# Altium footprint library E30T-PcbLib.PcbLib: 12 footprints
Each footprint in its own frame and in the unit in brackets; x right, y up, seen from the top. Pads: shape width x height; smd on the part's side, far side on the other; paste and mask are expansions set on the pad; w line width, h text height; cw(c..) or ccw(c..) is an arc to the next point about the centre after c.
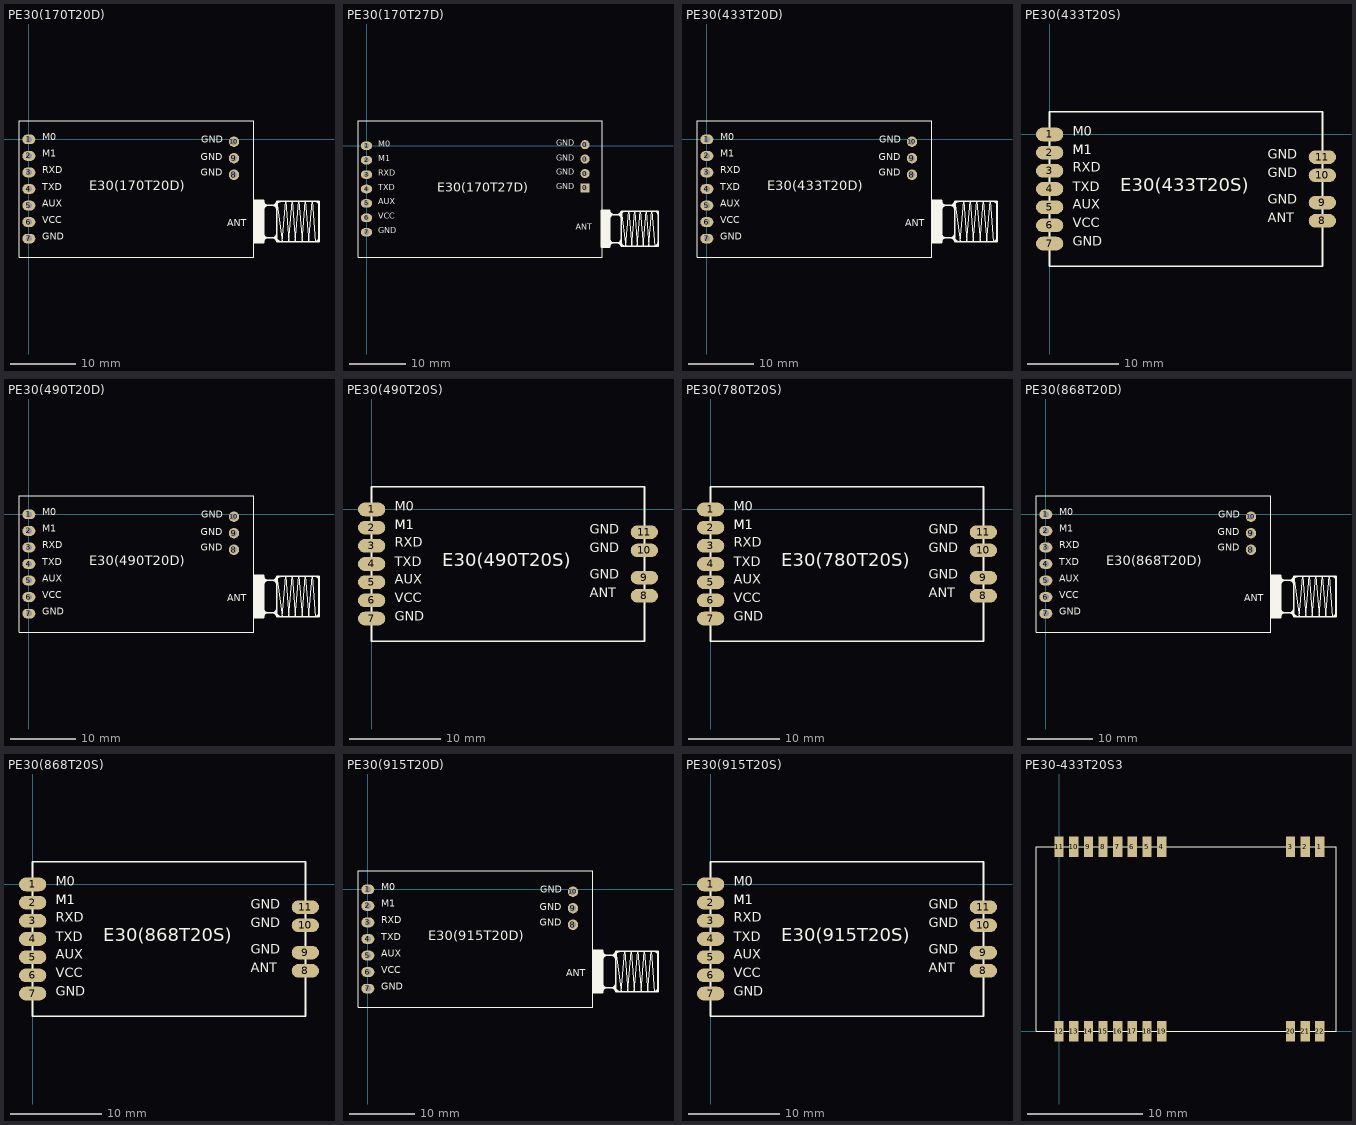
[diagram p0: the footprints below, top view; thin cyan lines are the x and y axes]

## PE30(170T20D) [mm] "36mm*21mm-D/SMA长度12.5mm"
pads (10):
  oval 2x1.5 hole 0.9: 1(0,0) 2(0,-2.54) 3(0,-5.08) 4(0,-7.62) 5(0,-10.16) 6(0,-12.7) 7(0,-15.24)
  round 1.6 hole 1: 8(31.49,-5.43) 9(31.49,-2.89) 10(31.49,-0.35)
Top Overlay:
  rectangle: 34.54,-15.865 36.04,-9.365
  rectangle: 34.54,-15.87 36.04,-9.37
  lines w0.1: 38.89,-15.72 38.04,-9.52 38.89,-15.72 ; 38.89,-15.72 39.41,-9.52 ; 38.89,-15.72 39.41,-9.52 ; 39.41,-9.52 39.92,-15.72 ; 39.41,-9.52 39.92,-15.72 ; 39.92,-15.72 40.43,-9.52 ; 39.92,-15.72 40.43,-9.52 ; 40.43,-9.52 40.91,-15.72 ; 40.43,-9.52 40.91,-15.72 ; 40.91,-15.72 41.43,-9.52 ; 40.91,-15.72 41.43,-9.52 ; 41.43,-9.52 41.94,-15.72 ; 41.43,-9.52 41.94,-15.72 ; 41.94,-15.72 42.43,-9.52 ; 41.94,-15.72 42.43,-9.52 ; 42.43,-9.52 42.95,-15.72 ; 42.43,-9.52 42.95,-15.72 ; 42.95,-15.72 43.47,-9.52 ; 42.95,-15.72 43.47,-9.52 ; 43.47,-9.52 43.98,-15.72 43.47,-9.52 ; -1.51,-18.12 -1.51,2.88 34.558,2.88 34.558,-18.12 -1.51,-18.12
  lines w0.254: 34.54,-15.87 34.54,-9.37 ; 34.54,-15.87 36.04,-15.87 ; 34.54,-15.87 34.54,-9.37 ; 34.54,-15.87 36.04,-15.87 ; 34.54,-9.37 36.04,-9.37 ; 34.54,-9.37 36.04,-9.37 ; 36.04,-15.87 36.04,-9.37 ; 36.04,-15.87 36.04,-9.37 ; 36.04,-14.47 ccw(c36.69,-14.47) 36.69,-15.12 ; 36.04,-14.47 ccw(c36.69,-14.47) 36.69,-15.12 ; 36.04,-14.47 36.04,-14.1 36.04,-14.47 ; 36.04,-10.82 cw(c36.74,-10.82) 36.74,-10.12 ; 36.04,-10.82 cw(c36.74,-10.82) 36.74,-10.12 ; 36.04,-10.82 36.04,-11.74 36.04,-10.82 ; 36.04,-9.49 ccw(c36.67,-9.49) 36.67,-10.12 ; 36.04,-9.49 ccw(c36.67,-9.49) 36.67,-10.12 ; 36.04,-9.49 36.04,-9.37 ; 36.04,-9.49 36.04,-9.37 ; 36.59,-15.12 ccw(c36.59,-15.67) 36.04,-15.67 cw(c36.59,-15.67) 36.59,-15.12 ; 36.59,-15.12 37.44,-15.12 ; 36.59,-15.12 37.44,-15.12 ; 36.67,-10.12 37.44,-10.12 ; 36.67,-10.12 37.44,-10.12 ; 36.69,-15.12 37.41,-15.12 ; 36.69,-15.12 37.41,-15.12 ; 36.74,-10.12 37.44,-10.12 ; 36.74,-10.12 37.44,-10.12 ; 37.41,-15.12 ccw(c37.41,-14.49) 38.04,-14.49 cw(c37.41,-14.49) 37.41,-15.12 ; 37.44,-15.12 cw(c37.44,-15.72) 38.04,-15.72 ; 37.44,-15.12 cw(c37.44,-15.72) 38.04,-15.72 ; 37.44,-10.12 ccw(c37.44,-9.52) 38.04,-9.52 ; 37.44,-10.12 cw(c37.44,-10.72) 38.04,-10.72 ccw(c37.44,-10.72) 37.44,-10.12 ; 37.44,-10.12 ccw(c37.44,-9.52) 38.04,-9.52 ; 38.04,-15.72 44.54,-15.72 ; 38.04,-15.72 38.04,-9.52 ; 38.04,-15.72 44.54,-15.72 ; 38.04,-15.72 38.04,-9.52 ; 38.04,-9.52 44.54,-9.52 ; 38.04,-9.52 44.54,-9.52 ; 38.72,-15.72 cw(c38.72,-15.04) 38.04,-15.04 ccw(c38.72,-15.04) 38.72,-15.72 ; 38.72,-15.72 38.87,-15.72 38.72,-15.72 ; 43.92,-15.72 ccw(c43.92,-15.1) 44.54,-15.1 cw(c43.92,-15.1) 43.92,-15.72 ; 43.92,-15.72 43.69,-15.72 43.92,-15.72 ; 44,-9.52 cw(c44,-10.06) 44.54,-10.06 ccw(c44,-10.06) 44,-9.52 ; 44,-9.52 43.6,-9.52 44,-9.52 ; 44.54,-15.72 44.54,-9.52 ; 44.54,-15.72 44.54,-9.52 ; 35.87,-15.12 38.04,-15.12 35.87,-15.12 ; 36.04,-10.12 38.04,-10.12 36.04,-10.12 ; 38.04,-10.13 cw(c38.65,-10.13) 38.65,-9.52 ccw(c38.65,-10.13) 38.04,-10.13
  text "E30(170T20D)" at 9.271,-8.382 h2.5
  text "GND" at 26.416,-5.969 h1.8
  text "GND" at 26.416,-3.556 h1.8
  text "GND" at 26.447,-0.921 h1.8
  text "ANT" at 30.48,-13.716 h1.8
  text "M0" at 2.063,-0.54 h1.8
  text "M1" at 2.063,-3.08 h1.8
  text "RXD" at 2.063,-5.62 h1.8
  text "TXD" at 2.063,-8.16 h1.8
  text "AUX" at 2.063,-10.7 h1.8
  text "VCC" at 2.063,-13.24 h1.8
  text "GND" at 2.063,-15.78 h1.8

## PE30(170T27D) [mm] "43MM*24mm-D//SMA长度12.5mm"
pads (11):
  rect 1.6x1.6 hole 0.9: 0(38.5,-7.43)
  round 1.6 hole 0.9: 0(38.5,-4.89) 0(38.5,-2.35) 0(38.5,0.19)
  oval 2x1.5 hole 0.9: 1(0,0) 2(0,-2.54) 3(0,-5.08) 4(0,-7.62) 5(0,-10.16) 6(0,-12.7) 7(0,-15.24)
Top Overlay:
  rectangle: 41.35,-17.87 42.85,-11.37
  rectangle: 41.35,-17.865 42.85,-11.365
  lines w0.1: 45.7,-17.72 46.22,-11.52 ; 45.7,-17.72 44.85,-11.52 45.7,-17.72 ; 45.7,-17.72 46.22,-11.52 ; 46.22,-11.52 46.73,-17.72 ; 46.22,-11.52 46.73,-17.72 ; 46.73,-17.72 47.24,-11.52 ; 46.73,-17.72 47.24,-11.52 ; 47.24,-11.52 47.72,-17.72 ; 47.24,-11.52 47.72,-17.72 ; 47.72,-17.72 48.24,-11.52 ; 47.72,-17.72 48.24,-11.52 ; 48.24,-11.52 48.75,-17.72 ; 48.24,-11.52 48.75,-17.72 ; 48.75,-17.72 49.24,-11.52 ; 48.75,-17.72 49.24,-11.52 ; 49.24,-11.52 49.76,-17.72 ; 49.24,-11.52 49.76,-17.72 ; 49.76,-17.72 50.28,-11.52 ; 49.76,-17.72 50.28,-11.52 ; 50.28,-11.52 50.79,-17.72 50.28,-11.52 ; -1.5,-19.62 41.5,-19.62 41.5,4.38 -1.5,4.38 -1.5,-19.62
  lines w0.254: 41.35,-17.87 42.85,-17.87 ; 41.35,-17.87 41.35,-11.37 ; 41.35,-17.87 42.85,-17.87 ; 41.35,-17.87 41.35,-11.37 ; 41.35,-11.37 42.85,-11.37 ; 41.35,-11.37 42.85,-11.37 ; 42.85,-17.87 42.85,-11.37 ; 42.85,-17.87 42.85,-11.37 ; 42.85,-16.47 ccw(c43.5,-16.47) 43.5,-17.12 ; 42.85,-16.47 ccw(c43.5,-16.47) 43.5,-17.12 ; 42.85,-16.47 42.85,-16.1 42.85,-16.47 ; 42.85,-12.82 cw(c43.55,-12.82) 43.55,-12.12 ; 42.85,-12.82 cw(c43.55,-12.82) 43.55,-12.12 ; 42.85,-12.82 42.85,-13.74 42.85,-12.82 ; 42.85,-11.49 ccw(c43.48,-11.49) 43.48,-12.12 ; 42.85,-11.49 ccw(c43.48,-11.49) 43.48,-12.12 ; 42.85,-11.49 42.85,-11.37 ; 42.85,-11.49 42.85,-11.37 ; 43.4,-17.12 ccw(c43.4,-17.67) 42.85,-17.67 cw(c43.4,-17.67) 43.4,-17.12 ; 43.4,-17.12 44.25,-17.12 ; 43.4,-17.12 44.25,-17.12 ; 43.48,-12.12 44.25,-12.12 ; 43.48,-12.12 44.25,-12.12 ; 43.5,-17.12 44.22,-17.12 ; 43.5,-17.12 44.22,-17.12 ; 43.55,-12.12 44.25,-12.12 ; 43.55,-12.12 44.25,-12.12 ; 44.22,-17.12 ccw(c44.22,-16.49) 44.85,-16.49 cw(c44.22,-16.49) 44.22,-17.12 ; 44.25,-17.12 cw(c44.25,-17.72) 44.85,-17.72 ; 44.25,-17.12 cw(c44.25,-17.72) 44.85,-17.72 ; 44.25,-12.12 cw(c44.25,-12.72) 44.85,-12.72 ccw(c44.25,-12.72) 44.25,-12.12 ; 44.25,-12.12 ccw(c44.25,-11.52) 44.85,-11.52 ; 44.25,-12.12 ccw(c44.25,-11.52) 44.85,-11.52 ; 44.85,-17.72 44.85,-11.52 ; 44.85,-17.72 51.35,-17.72 ; 44.85,-17.72 44.85,-11.52 ; 44.85,-17.72 51.35,-17.72 ; 44.85,-11.52 51.35,-11.52 ; 44.85,-11.52 51.35,-11.52 ; 45.53,-17.72 cw(c45.53,-17.04) 44.85,-17.04 ccw(c45.53,-17.04) 45.53,-17.72 ; 45.53,-17.72 45.68,-17.72 45.53,-17.72 ; 50.73,-17.72 ccw(c50.73,-17.1) 51.35,-17.1 cw(c50.73,-17.1) 50.73,-17.72 ; 50.73,-17.72 50.5,-17.72 50.73,-17.72 ; 50.81,-11.52 cw(c50.81,-12.06) 51.35,-12.06 ccw(c50.81,-12.06) 50.81,-11.52 ; 50.81,-11.52 50.41,-11.52 50.81,-11.52 ; 51.35,-17.72 51.35,-11.52 ; 51.35,-17.72 51.35,-11.52 ; 42.68,-17.12 44.85,-17.12 42.68,-17.12 ; 42.85,-12.12 44.85,-12.12 42.85,-12.12 ; 44.85,-12.13 cw(c45.46,-12.13) 45.46,-11.52 ccw(c45.46,-12.13) 44.85,-12.13
  text "E30(170T27D)" at 12.446,-8.763 h2.8
  text "ANT" at 36.83,-15.19 h1.8
  text "M0" at 2.063,-0.54 h1.8
  text "M1" at 2.063,-3.08 h1.8
  text "RXD" at 2.063,-5.62 h1.8
  text "TXD" at 2.063,-8.16 h1.8
  text "AUX" at 2.063,-10.7 h1.8
  text "VCC" at 2.063,-13.24 h1.8
  text "GND" at 2.063,-15.78 h1.8
  text "GND" at 33.426,-5.429 h1.8
  text "GND" at 33.426,-3.016 h1.8
  text "GND" at 33.457,-0.381 h1.8
  text "GND" at 33.457,-8.001 h1.8

## PE30(433T20D) [mm] "36mm*21mm-D//SMA长度12.5mm"
pads (10):
  oval 2x1.5 hole 0.9: 1(0,0) 2(0,-2.54) 3(0,-5.08) 4(0,-7.62) 5(0,-10.16) 6(0,-12.7) 7(0,-15.24)
  round 1.6 hole 1: 8(31.49,-5.43) 9(31.49,-2.89) 10(31.49,-0.35)
Top Overlay:
  rectangle: 34.54,-15.87 36.04,-9.37
  rectangle: 34.54,-15.865 36.04,-9.365
  lines w0.1: 38.89,-15.72 39.41,-9.52 ; 38.89,-15.72 38.04,-9.52 38.89,-15.72 ; 38.89,-15.72 39.41,-9.52 ; 39.41,-9.52 39.92,-15.72 ; 39.41,-9.52 39.92,-15.72 ; 39.92,-15.72 40.43,-9.52 ; 39.92,-15.72 40.43,-9.52 ; 40.43,-9.52 40.91,-15.72 ; 40.43,-9.52 40.91,-15.72 ; 40.91,-15.72 41.43,-9.52 ; 40.91,-15.72 41.43,-9.52 ; 41.43,-9.52 41.94,-15.72 ; 41.43,-9.52 41.94,-15.72 ; 41.94,-15.72 42.43,-9.52 ; 41.94,-15.72 42.43,-9.52 ; 42.43,-9.52 42.95,-15.72 ; 42.43,-9.52 42.95,-15.72 ; 42.95,-15.72 43.47,-9.52 ; 42.95,-15.72 43.47,-9.52 ; 43.47,-9.52 43.98,-15.72 43.47,-9.52 ; -1.51,-18.12 34.558,-18.12 34.558,2.88 -1.51,2.88 -1.51,-18.12
  lines w0.254: 34.54,-15.87 36.04,-15.87 ; 34.54,-15.87 34.54,-9.37 ; 34.54,-15.87 36.04,-15.87 ; 34.54,-15.87 34.54,-9.37 ; 34.54,-9.37 36.04,-9.37 ; 34.54,-9.37 36.04,-9.37 ; 36.04,-15.87 36.04,-9.37 ; 36.04,-15.87 36.04,-9.37 ; 36.04,-14.47 ccw(c36.69,-14.47) 36.69,-15.12 ; 36.04,-14.47 ccw(c36.69,-14.47) 36.69,-15.12 ; 36.04,-14.47 36.04,-14.1 36.04,-14.47 ; 36.04,-10.82 cw(c36.74,-10.82) 36.74,-10.12 ; 36.04,-10.82 cw(c36.74,-10.82) 36.74,-10.12 ; 36.04,-10.82 36.04,-11.74 36.04,-10.82 ; 36.04,-9.49 ccw(c36.67,-9.49) 36.67,-10.12 ; 36.04,-9.49 ccw(c36.67,-9.49) 36.67,-10.12 ; 36.04,-9.49 36.04,-9.37 ; 36.04,-9.49 36.04,-9.37 ; 36.59,-15.12 ccw(c36.59,-15.67) 36.04,-15.67 cw(c36.59,-15.67) 36.59,-15.12 ; 36.59,-15.12 37.44,-15.12 ; 36.59,-15.12 37.44,-15.12 ; 36.67,-10.12 37.44,-10.12 ; 36.67,-10.12 37.44,-10.12 ; 36.69,-15.12 37.41,-15.12 ; 36.69,-15.12 37.41,-15.12 ; 36.74,-10.12 37.44,-10.12 ; 36.74,-10.12 37.44,-10.12 ; 37.41,-15.12 ccw(c37.41,-14.49) 38.04,-14.49 cw(c37.41,-14.49) 37.41,-15.12 ; 37.44,-15.12 cw(c37.44,-15.72) 38.04,-15.72 ; 37.44,-15.12 cw(c37.44,-15.72) 38.04,-15.72 ; 37.44,-10.12 cw(c37.44,-10.72) 38.04,-10.72 ccw(c37.44,-10.72) 37.44,-10.12 ; 37.44,-10.12 ccw(c37.44,-9.52) 38.04,-9.52 ; 37.44,-10.12 ccw(c37.44,-9.52) 38.04,-9.52 ; 38.04,-15.72 38.04,-9.52 ; 38.04,-15.72 44.54,-15.72 ; 38.04,-15.72 38.04,-9.52 ; 38.04,-15.72 44.54,-15.72 ; 38.04,-9.52 44.54,-9.52 ; 38.04,-9.52 44.54,-9.52 ; 38.72,-15.72 cw(c38.72,-15.04) 38.04,-15.04 ccw(c38.72,-15.04) 38.72,-15.72 ; 38.72,-15.72 38.87,-15.72 38.72,-15.72 ; 43.92,-15.72 ccw(c43.92,-15.1) 44.54,-15.1 cw(c43.92,-15.1) 43.92,-15.72 ; 43.92,-15.72 43.69,-15.72 43.92,-15.72 ; 44,-9.52 cw(c44,-10.06) 44.54,-10.06 ccw(c44,-10.06) 44,-9.52 ; 44,-9.52 43.6,-9.52 44,-9.52 ; 44.54,-15.72 44.54,-9.52 ; 44.54,-15.72 44.54,-9.52 ; 35.87,-15.12 38.04,-15.12 35.87,-15.12 ; 36.04,-10.12 38.04,-10.12 36.04,-10.12 ; 38.04,-10.13 cw(c38.65,-10.13) 38.65,-9.52 ccw(c38.65,-10.13) 38.04,-10.13
  text "GND" at 2.063,-15.78 h1.8
  text "VCC" at 2.063,-13.24 h1.8
  text "AUX" at 2.063,-10.7 h1.8
  text "TXD" at 2.063,-8.16 h1.8
  text "RXD" at 2.063,-5.62 h1.8
  text "M1" at 2.063,-3.08 h1.8
  text "M0" at 2.063,-0.54 h1.8
  text "ANT" at 30.48,-13.716 h1.8
  text "GND" at 26.447,-0.921 h1.8
  text "GND" at 26.416,-3.556 h1.8
  text "GND" at 26.416,-5.969 h1.8
  text "E30(433T20D)" at 9.271,-8.382 h2.5

## PE30(433T20S) [mm] "30mm*17mm*3.5mm-S"
pads (11):
  oval 3x1.5 smd: 1(0,0) 2(0,-2) 3(0,-4) 4(0,-6) 5(0,-8) 6(0,-10) 7(0,-12) 8(30,-9.5) 9(30,-7.5) 10(30,-4.5) 11(30,-2.5)
Top Overlay:
  lines w0.2: 0,-14.5 0,2.5 30,2.5 30,-14.5 0,-14.5
  text "E30(433T20S)" at 7.761,-6.762 h2.5
  text "AUX" at 2.554,-8.54 h1.8
  text "M0" at 2.554,-0.539 h1.8
  text "M1" at 2.554,-2.571 h1.8
  text "M1" at 2.554,-2.571 h1.8
  text "RXD" at 2.554,-4.476 h1.8
  text "TXD" at 2.554,-6.635 h1.8
  text "VCC" at 2.554,-10.572 h1.8
  text "GND" at 2.554,-12.604 h1.8
  text "GND" at 24.017,-3.079 h1.8
  text "GND" at 24.017,-5.111 h1.8
  text "GND" at 24.017,-8.032 h1.8
  text "ANT" at 24.017,-10.064 h1.8

## PE30(490T20D) [mm] "36mm*21mm-D//SMA长度12.5mm"
pads (10):
  oval 2x1.5 hole 0.9: 1(0,0) 2(0,-2.54) 3(0,-5.08) 4(0,-7.62) 5(0,-10.16) 6(0,-12.7) 7(0,-15.24)
  round 1.6 hole 1: 8(31.49,-5.43) 9(31.49,-2.89) 10(31.49,-0.35)
Top Overlay:
  rectangle: 34.54,-15.865 36.04,-9.365
  rectangle: 34.54,-15.87 36.04,-9.37
  lines w0.1: 38.89,-15.72 38.04,-9.52 38.89,-15.72 ; 38.89,-15.72 39.41,-9.52 ; 38.89,-15.72 39.41,-9.52 ; 39.41,-9.52 39.92,-15.72 ; 39.41,-9.52 39.92,-15.72 ; 39.92,-15.72 40.43,-9.52 ; 39.92,-15.72 40.43,-9.52 ; 40.43,-9.52 40.91,-15.72 ; 40.43,-9.52 40.91,-15.72 ; 40.91,-15.72 41.43,-9.52 ; 40.91,-15.72 41.43,-9.52 ; 41.43,-9.52 41.94,-15.72 ; 41.43,-9.52 41.94,-15.72 ; 41.94,-15.72 42.43,-9.52 ; 41.94,-15.72 42.43,-9.52 ; 42.43,-9.52 42.95,-15.72 ; 42.43,-9.52 42.95,-15.72 ; 42.95,-15.72 43.47,-9.52 ; 42.95,-15.72 43.47,-9.52 ; 43.47,-9.52 43.98,-15.72 43.47,-9.52 ; -1.51,-18.12 -1.51,2.88 34.558,2.88 34.558,-18.12 -1.51,-18.12
  lines w0.254: 34.54,-15.87 34.54,-9.37 ; 34.54,-15.87 36.04,-15.87 ; 34.54,-15.87 34.54,-9.37 ; 34.54,-15.87 36.04,-15.87 ; 34.54,-9.37 36.04,-9.37 ; 34.54,-9.37 36.04,-9.37 ; 36.04,-15.87 36.04,-9.37 ; 36.04,-15.87 36.04,-9.37 ; 36.04,-14.47 ccw(c36.69,-14.47) 36.69,-15.12 ; 36.04,-14.47 ccw(c36.69,-14.47) 36.69,-15.12 ; 36.04,-14.47 36.04,-14.1 36.04,-14.47 ; 36.04,-10.82 cw(c36.74,-10.82) 36.74,-10.12 ; 36.04,-10.82 cw(c36.74,-10.82) 36.74,-10.12 ; 36.04,-10.82 36.04,-11.74 36.04,-10.82 ; 36.04,-9.49 ccw(c36.67,-9.49) 36.67,-10.12 ; 36.04,-9.49 ccw(c36.67,-9.49) 36.67,-10.12 ; 36.04,-9.49 36.04,-9.37 ; 36.04,-9.49 36.04,-9.37 ; 36.59,-15.12 ccw(c36.59,-15.67) 36.04,-15.67 cw(c36.59,-15.67) 36.59,-15.12 ; 36.59,-15.12 37.44,-15.12 ; 36.59,-15.12 37.44,-15.12 ; 36.67,-10.12 37.44,-10.12 ; 36.67,-10.12 37.44,-10.12 ; 36.69,-15.12 37.41,-15.12 ; 36.69,-15.12 37.41,-15.12 ; 36.74,-10.12 37.44,-10.12 ; 36.74,-10.12 37.44,-10.12 ; 37.41,-15.12 ccw(c37.41,-14.49) 38.04,-14.49 cw(c37.41,-14.49) 37.41,-15.12 ; 37.44,-15.12 cw(c37.44,-15.72) 38.04,-15.72 ; 37.44,-15.12 cw(c37.44,-15.72) 38.04,-15.72 ; 37.44,-10.12 ccw(c37.44,-9.52) 38.04,-9.52 ; 37.44,-10.12 cw(c37.44,-10.72) 38.04,-10.72 ccw(c37.44,-10.72) 37.44,-10.12 ; 37.44,-10.12 ccw(c37.44,-9.52) 38.04,-9.52 ; 38.04,-15.72 44.54,-15.72 ; 38.04,-15.72 38.04,-9.52 ; 38.04,-15.72 44.54,-15.72 ; 38.04,-15.72 38.04,-9.52 ; 38.04,-9.52 44.54,-9.52 ; 38.04,-9.52 44.54,-9.52 ; 38.72,-15.72 cw(c38.72,-15.04) 38.04,-15.04 ccw(c38.72,-15.04) 38.72,-15.72 ; 38.72,-15.72 38.87,-15.72 38.72,-15.72 ; 43.92,-15.72 ccw(c43.92,-15.1) 44.54,-15.1 cw(c43.92,-15.1) 43.92,-15.72 ; 43.92,-15.72 43.69,-15.72 43.92,-15.72 ; 44,-9.52 cw(c44,-10.06) 44.54,-10.06 ccw(c44,-10.06) 44,-9.52 ; 44,-9.52 43.6,-9.52 44,-9.52 ; 44.54,-15.72 44.54,-9.52 ; 44.54,-15.72 44.54,-9.52 ; 35.87,-15.12 38.04,-15.12 35.87,-15.12 ; 36.04,-10.12 38.04,-10.12 36.04,-10.12 ; 38.04,-10.13 cw(c38.65,-10.13) 38.65,-9.52 ccw(c38.65,-10.13) 38.04,-10.13
  text "E30(490T20D)" at 9.271,-8.382 h2.5
  text "GND" at 26.416,-5.969 h1.8
  text "GND" at 26.416,-3.556 h1.8
  text "GND" at 26.447,-0.921 h1.8
  text "ANT" at 30.48,-13.716 h1.8
  text "M0" at 2.063,-0.54 h1.8
  text "M1" at 2.063,-3.08 h1.8
  text "RXD" at 2.063,-5.62 h1.8
  text "TXD" at 2.063,-8.16 h1.8
  text "AUX" at 2.063,-10.7 h1.8
  text "VCC" at 2.063,-13.24 h1.8
  text "GND" at 2.063,-15.78 h1.8

## PE30(490T20S) [mm] "30mm*17mm*3.5mm-S"
pads (11):
  oval 3x1.5 smd: 1(0,0) 2(0,-2) 3(0,-4) 4(0,-6) 5(0,-8) 6(0,-10) 7(0,-12) 8(30,-9.5) 9(30,-7.5) 10(30,-4.5) 11(30,-2.5)
Top Overlay:
  lines w0.2: 0,-14.5 30,-14.5 30,2.5 0,2.5 0,-14.5
  text "ANT" at 24.017,-10.064 h1.8
  text "GND" at 24.017,-8.032 h1.8
  text "GND" at 24.017,-5.111 h1.8
  text "GND" at 24.017,-3.079 h1.8
  text "GND" at 2.554,-12.604 h1.8
  text "VCC" at 2.554,-10.572 h1.8
  text "TXD" at 2.554,-6.635 h1.8
  text "RXD" at 2.554,-4.476 h1.8
  text "M1" at 2.554,-2.571 h1.8
  text "M1" at 2.554,-2.571 h1.8
  text "M0" at 2.554,-0.539 h1.8
  text "AUX" at 2.554,-8.54 h1.8
  text "E30(490T20S)" at 7.761,-6.762 h2.5

## PE30(780T20S) [mm] "30mm*17mm*3.5mm-S"
pads (11):
  oval 3x1.5 smd: 1(0,0) 2(0,-2) 3(0,-4) 4(0,-6) 5(0,-8) 6(0,-10) 7(0,-12) 8(30,-9.5) 9(30,-7.5) 10(30,-4.5) 11(30,-2.5)
Top Overlay:
  lines w0.2: 0,-14.5 30,-14.5 30,2.5 0,2.5 0,-14.5
  text "ANT" at 24.017,-10.064 h1.8
  text "GND" at 24.017,-8.032 h1.8
  text "GND" at 24.017,-5.111 h1.8
  text "GND" at 24.017,-3.079 h1.8
  text "GND" at 2.554,-12.604 h1.8
  text "VCC" at 2.554,-10.572 h1.8
  text "TXD" at 2.554,-6.635 h1.8
  text "RXD" at 2.554,-4.476 h1.8
  text "M1" at 2.554,-2.571 h1.8
  text "M1" at 2.554,-2.571 h1.8
  text "M0" at 2.554,-0.539 h1.8
  text "AUX" at 2.554,-8.54 h1.8
  text "E30(780T20S)" at 7.761,-6.762 h2.5

## PE30(868T20D) [mm] "36mm*21mm-D//SMA长度12.5mm"
pads (10):
  oval 2x1.5 hole 0.9: 1(0,0) 2(0,-2.54) 3(0,-5.08) 4(0,-7.62) 5(0,-10.16) 6(0,-12.7) 7(0,-15.24)
  round 1.6 hole 1: 8(31.49,-5.43) 9(31.49,-2.89) 10(31.49,-0.35)
Top Overlay:
  rectangle: 34.54,-15.87 36.04,-9.37
  rectangle: 34.54,-15.865 36.04,-9.365
  lines w0.1: 38.89,-15.72 39.41,-9.52 ; 38.89,-15.72 38.04,-9.52 38.89,-15.72 ; 38.89,-15.72 39.41,-9.52 ; 39.41,-9.52 39.92,-15.72 ; 39.41,-9.52 39.92,-15.72 ; 39.92,-15.72 40.43,-9.52 ; 39.92,-15.72 40.43,-9.52 ; 40.43,-9.52 40.91,-15.72 ; 40.43,-9.52 40.91,-15.72 ; 40.91,-15.72 41.43,-9.52 ; 40.91,-15.72 41.43,-9.52 ; 41.43,-9.52 41.94,-15.72 ; 41.43,-9.52 41.94,-15.72 ; 41.94,-15.72 42.43,-9.52 ; 41.94,-15.72 42.43,-9.52 ; 42.43,-9.52 42.95,-15.72 ; 42.43,-9.52 42.95,-15.72 ; 42.95,-15.72 43.47,-9.52 ; 42.95,-15.72 43.47,-9.52 ; 43.47,-9.52 43.98,-15.72 43.47,-9.52 ; -1.51,-18.12 34.558,-18.12 34.558,2.88 -1.51,2.88 -1.51,-18.12
  lines w0.254: 34.54,-15.87 36.04,-15.87 ; 34.54,-15.87 34.54,-9.37 ; 34.54,-15.87 36.04,-15.87 ; 34.54,-15.87 34.54,-9.37 ; 34.54,-9.37 36.04,-9.37 ; 34.54,-9.37 36.04,-9.37 ; 36.04,-15.87 36.04,-9.37 ; 36.04,-15.87 36.04,-9.37 ; 36.04,-14.47 ccw(c36.69,-14.47) 36.69,-15.12 ; 36.04,-14.47 ccw(c36.69,-14.47) 36.69,-15.12 ; 36.04,-14.47 36.04,-14.1 36.04,-14.47 ; 36.04,-10.82 cw(c36.74,-10.82) 36.74,-10.12 ; 36.04,-10.82 cw(c36.74,-10.82) 36.74,-10.12 ; 36.04,-10.82 36.04,-11.74 36.04,-10.82 ; 36.04,-9.49 ccw(c36.67,-9.49) 36.67,-10.12 ; 36.04,-9.49 ccw(c36.67,-9.49) 36.67,-10.12 ; 36.04,-9.49 36.04,-9.37 ; 36.04,-9.49 36.04,-9.37 ; 36.59,-15.12 ccw(c36.59,-15.67) 36.04,-15.67 cw(c36.59,-15.67) 36.59,-15.12 ; 36.59,-15.12 37.44,-15.12 ; 36.59,-15.12 37.44,-15.12 ; 36.67,-10.12 37.44,-10.12 ; 36.67,-10.12 37.44,-10.12 ; 36.69,-15.12 37.41,-15.12 ; 36.69,-15.12 37.41,-15.12 ; 36.74,-10.12 37.44,-10.12 ; 36.74,-10.12 37.44,-10.12 ; 37.41,-15.12 ccw(c37.41,-14.49) 38.04,-14.49 cw(c37.41,-14.49) 37.41,-15.12 ; 37.44,-15.12 cw(c37.44,-15.72) 38.04,-15.72 ; 37.44,-15.12 cw(c37.44,-15.72) 38.04,-15.72 ; 37.44,-10.12 cw(c37.44,-10.72) 38.04,-10.72 ccw(c37.44,-10.72) 37.44,-10.12 ; 37.44,-10.12 ccw(c37.44,-9.52) 38.04,-9.52 ; 37.44,-10.12 ccw(c37.44,-9.52) 38.04,-9.52 ; 38.04,-15.72 38.04,-9.52 ; 38.04,-15.72 44.54,-15.72 ; 38.04,-15.72 38.04,-9.52 ; 38.04,-15.72 44.54,-15.72 ; 38.04,-9.52 44.54,-9.52 ; 38.04,-9.52 44.54,-9.52 ; 38.72,-15.72 cw(c38.72,-15.04) 38.04,-15.04 ccw(c38.72,-15.04) 38.72,-15.72 ; 38.72,-15.72 38.87,-15.72 38.72,-15.72 ; 43.92,-15.72 ccw(c43.92,-15.1) 44.54,-15.1 cw(c43.92,-15.1) 43.92,-15.72 ; 43.92,-15.72 43.69,-15.72 43.92,-15.72 ; 44,-9.52 cw(c44,-10.06) 44.54,-10.06 ccw(c44,-10.06) 44,-9.52 ; 44,-9.52 43.6,-9.52 44,-9.52 ; 44.54,-15.72 44.54,-9.52 ; 44.54,-15.72 44.54,-9.52 ; 35.87,-15.12 38.04,-15.12 35.87,-15.12 ; 36.04,-10.12 38.04,-10.12 36.04,-10.12 ; 38.04,-10.13 cw(c38.65,-10.13) 38.65,-9.52 ccw(c38.65,-10.13) 38.04,-10.13
  text "GND" at 2.063,-15.78 h1.8
  text "VCC" at 2.063,-13.24 h1.8
  text "AUX" at 2.063,-10.7 h1.8
  text "TXD" at 2.063,-8.16 h1.8
  text "RXD" at 2.063,-5.62 h1.8
  text "M1" at 2.063,-3.08 h1.8
  text "M0" at 2.063,-0.54 h1.8
  text "ANT" at 30.48,-13.716 h1.8
  text "GND" at 26.447,-0.921 h1.8
  text "GND" at 26.416,-3.556 h1.8
  text "GND" at 26.416,-5.969 h1.8
  text "E30(868T20D)" at 9.271,-8.382 h2.5

## PE30(868T20S) [mm] "30mm*17mm*3.5mm-S"
pads (11):
  oval 3x1.5 smd: 1(0,0) 2(0,-2) 3(0,-4) 4(0,-6) 5(0,-8) 6(0,-10) 7(0,-12) 8(30,-9.5) 9(30,-7.5) 10(30,-4.5) 11(30,-2.5)
Top Overlay:
  lines w0.2: 0,-14.5 30,-14.5 30,2.5 0,2.5 0,-14.5
  text "ANT" at 24.017,-10.064 h1.8
  text "GND" at 24.017,-8.032 h1.8
  text "GND" at 24.017,-5.111 h1.8
  text "GND" at 24.017,-3.079 h1.8
  text "GND" at 2.554,-12.604 h1.8
  text "VCC" at 2.554,-10.572 h1.8
  text "TXD" at 2.554,-6.635 h1.8
  text "RXD" at 2.554,-4.476 h1.8
  text "M1" at 2.554,-2.571 h1.8
  text "M1" at 2.554,-2.571 h1.8
  text "M0" at 2.554,-0.539 h1.8
  text "AUX" at 2.554,-8.54 h1.8
  text "E30(868T20S)" at 7.761,-6.762 h2.5

## PE30(915T20D) [mm] "36mm*21mm-D//SMA长度12.5mm"
pads (10):
  oval 2x1.5 hole 0.9: 1(0,0) 2(0,-2.54) 3(0,-5.08) 4(0,-7.62) 5(0,-10.16) 6(0,-12.7) 7(0,-15.24)
  round 1.6 hole 1: 8(31.49,-5.43) 9(31.49,-2.89) 10(31.49,-0.35)
Top Overlay:
  rectangle: 34.54,-15.87 36.04,-9.37
  rectangle: 34.54,-15.865 36.04,-9.365
  lines w0.1: 38.89,-15.72 39.41,-9.52 ; 38.89,-15.72 38.04,-9.52 38.89,-15.72 ; 38.89,-15.72 39.41,-9.52 ; 39.41,-9.52 39.92,-15.72 ; 39.41,-9.52 39.92,-15.72 ; 39.92,-15.72 40.43,-9.52 ; 39.92,-15.72 40.43,-9.52 ; 40.43,-9.52 40.91,-15.72 ; 40.43,-9.52 40.91,-15.72 ; 40.91,-15.72 41.43,-9.52 ; 40.91,-15.72 41.43,-9.52 ; 41.43,-9.52 41.94,-15.72 ; 41.43,-9.52 41.94,-15.72 ; 41.94,-15.72 42.43,-9.52 ; 41.94,-15.72 42.43,-9.52 ; 42.43,-9.52 42.95,-15.72 ; 42.43,-9.52 42.95,-15.72 ; 42.95,-15.72 43.47,-9.52 ; 42.95,-15.72 43.47,-9.52 ; 43.47,-9.52 43.98,-15.72 43.47,-9.52 ; -1.51,-18.12 34.558,-18.12 34.558,2.88 -1.51,2.88 -1.51,-18.12
  lines w0.254: 34.54,-15.87 36.04,-15.87 ; 34.54,-15.87 34.54,-9.37 ; 34.54,-15.87 36.04,-15.87 ; 34.54,-15.87 34.54,-9.37 ; 34.54,-9.37 36.04,-9.37 ; 34.54,-9.37 36.04,-9.37 ; 36.04,-15.87 36.04,-9.37 ; 36.04,-15.87 36.04,-9.37 ; 36.04,-14.47 ccw(c36.69,-14.47) 36.69,-15.12 ; 36.04,-14.47 ccw(c36.69,-14.47) 36.69,-15.12 ; 36.04,-14.47 36.04,-14.1 36.04,-14.47 ; 36.04,-10.82 cw(c36.74,-10.82) 36.74,-10.12 ; 36.04,-10.82 cw(c36.74,-10.82) 36.74,-10.12 ; 36.04,-10.82 36.04,-11.74 36.04,-10.82 ; 36.04,-9.49 ccw(c36.67,-9.49) 36.67,-10.12 ; 36.04,-9.49 ccw(c36.67,-9.49) 36.67,-10.12 ; 36.04,-9.49 36.04,-9.37 ; 36.04,-9.49 36.04,-9.37 ; 36.59,-15.12 ccw(c36.59,-15.67) 36.04,-15.67 cw(c36.59,-15.67) 36.59,-15.12 ; 36.59,-15.12 37.44,-15.12 ; 36.59,-15.12 37.44,-15.12 ; 36.67,-10.12 37.44,-10.12 ; 36.67,-10.12 37.44,-10.12 ; 36.69,-15.12 37.41,-15.12 ; 36.69,-15.12 37.41,-15.12 ; 36.74,-10.12 37.44,-10.12 ; 36.74,-10.12 37.44,-10.12 ; 37.41,-15.12 ccw(c37.41,-14.49) 38.04,-14.49 cw(c37.41,-14.49) 37.41,-15.12 ; 37.44,-15.12 cw(c37.44,-15.72) 38.04,-15.72 ; 37.44,-15.12 cw(c37.44,-15.72) 38.04,-15.72 ; 37.44,-10.12 cw(c37.44,-10.72) 38.04,-10.72 ccw(c37.44,-10.72) 37.44,-10.12 ; 37.44,-10.12 ccw(c37.44,-9.52) 38.04,-9.52 ; 37.44,-10.12 ccw(c37.44,-9.52) 38.04,-9.52 ; 38.04,-15.72 38.04,-9.52 ; 38.04,-15.72 44.54,-15.72 ; 38.04,-15.72 38.04,-9.52 ; 38.04,-15.72 44.54,-15.72 ; 38.04,-9.52 44.54,-9.52 ; 38.04,-9.52 44.54,-9.52 ; 38.72,-15.72 cw(c38.72,-15.04) 38.04,-15.04 ccw(c38.72,-15.04) 38.72,-15.72 ; 38.72,-15.72 38.87,-15.72 38.72,-15.72 ; 43.92,-15.72 ccw(c43.92,-15.1) 44.54,-15.1 cw(c43.92,-15.1) 43.92,-15.72 ; 43.92,-15.72 43.69,-15.72 43.92,-15.72 ; 44,-9.52 cw(c44,-10.06) 44.54,-10.06 ccw(c44,-10.06) 44,-9.52 ; 44,-9.52 43.6,-9.52 44,-9.52 ; 44.54,-15.72 44.54,-9.52 ; 44.54,-15.72 44.54,-9.52 ; 35.87,-15.12 38.04,-15.12 35.87,-15.12 ; 36.04,-10.12 38.04,-10.12 36.04,-10.12 ; 38.04,-10.13 cw(c38.65,-10.13) 38.65,-9.52 ccw(c38.65,-10.13) 38.04,-10.13
  text "GND" at 2.063,-15.78 h1.8
  text "VCC" at 2.063,-13.24 h1.8
  text "AUX" at 2.063,-10.7 h1.8
  text "TXD" at 2.063,-8.16 h1.8
  text "RXD" at 2.063,-5.62 h1.8
  text "M1" at 2.063,-3.08 h1.8
  text "M0" at 2.063,-0.54 h1.8
  text "ANT" at 30.48,-13.716 h1.8
  text "GND" at 26.447,-0.921 h1.8
  text "GND" at 26.416,-3.556 h1.8
  text "GND" at 26.416,-5.969 h1.8
  text "E30(915T20D)" at 9.271,-8.382 h2.5

## PE30(915T20S) [mm] "30mm*17mm*3.5mm-S"
pads (11):
  oval 3x1.5 smd: 1(0,0) 2(0,-2) 3(0,-4) 4(0,-6) 5(0,-8) 6(0,-10) 7(0,-12) 8(30,-9.5) 9(30,-7.5) 10(30,-4.5) 11(30,-2.5)
Top Overlay:
  lines w0.2: 0,-14.5 30,-14.5 30,2.5 0,2.5 0,-14.5
  text "ANT" at 24.017,-10.064 h1.8
  text "GND" at 24.017,-8.032 h1.8
  text "GND" at 24.017,-5.111 h1.8
  text "GND" at 24.017,-3.079 h1.8
  text "GND" at 2.554,-12.604 h1.8
  text "VCC" at 2.554,-10.572 h1.8
  text "TXD" at 2.554,-6.635 h1.8
  text "RXD" at 2.554,-4.476 h1.8
  text "M1" at 2.554,-2.571 h1.8
  text "M1" at 2.554,-2.571 h1.8
  text "M0" at 2.554,-0.539 h1.8
  text "AUX" at 2.554,-8.54 h1.8
  text "E30(915T20S)" at 7.761,-6.762 h2.5

## PE30-433T20S3 [mm]
pads (22):
  rect 0.8x1.8 smd: 1(22.6,16) 2(21.33,16) 3(20.06,16) 4(8.89,16) 5(7.62,16) 6(6.35,16) 7(5.08,16) 8(3.81,16) 9(2.54,16) 10(1.27,16) 11(0,16) 12(0,0) 13(1.27,0) 14(2.54,0) 15(3.81,0) 16(5.08,0) 17(6.35,0) 18(7.62,0) 19(8.89,0) 20(20.06,0) 21(21.33,0) 22(22.6,0)
Top Overlay:
  lines w0.1: -2,0 -2,16 24,16 24,0 -2,0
